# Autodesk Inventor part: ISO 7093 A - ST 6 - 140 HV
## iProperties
Created: 2007-03
Part Number: ISO 7093 A - ST 6 - 140 HV
Material: Acier inoxydable
Description: Rondelle plates - Série grandes dimensions - Produit de classe A
Document SubType Name: Modeling
Standard: ISO 7093 A
Designer: EF
Standard Revision: Première édition 2000-06-01
Standards Organization: ISO
Language: fr-FR
Size Designation: ST 6 - 140 HV - A
Categories: <MemberInstance><Categories><Category DisplayName="Visserie" InternalName="e4da775c-781d-43d5-af7c-5136215cf5a6" Mnemonic="FSTN"><Category DisplayName="Rondelle
Density: 1 g/cm^3
IsCustomPart: 0
Author: EF
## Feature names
1. Corps [Extrusion]
